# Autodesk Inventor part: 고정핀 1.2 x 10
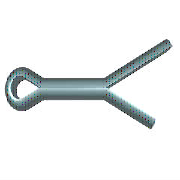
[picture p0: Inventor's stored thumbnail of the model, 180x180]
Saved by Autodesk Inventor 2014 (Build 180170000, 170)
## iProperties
IsCustomPart: 1
Created: 2012-02
Part Number: 고정핀 1.2 x 10
Material: 강철
Description: 분할 핀
Document SubType Name: Modeling
Standard: ISO 1234
Designer: test
Standard Revision: Second edition 1997-11-01
Standards Organization: ISO
Language: ko-KR
Size Designation: 1.2 x 10
Categories: <MemberInstance><Categories><Category DisplayName="조임쇠" InternalName="e4da775c-781d-43d5-af7c-5136215cf5a6" Mnemonic="FSTN"><Category DisplayName="핀" InternalNa
Density: 7.85 g/cm^3
Appearance: 강철
Author: test
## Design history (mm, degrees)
sketch "스케치1"
  geometry: L1 (0, 0.5)-(5, 0.5); L2 (0, -0.5)-(5, -0.5); L3 (5, 0.5)-(10, 2.416); L4 (10, 2.416)-(10.167, 1.98); L5 (10.167, 1.98)-(5, 0); L6 (5, 0)-(12.667, -2.937); L7 (12.667, -2.937)-(12.5, -3.373); L8 (12.5, -3.373)-(5, -0.5); L9 (0, 0)-(-1.875, -0.484); L10 (0, 0)-(-1.875, 0.484); L11 (0, 0.5)-(0, -0.5); L12 (0, 0.5)-(-1.742, 0.966); L13 (0, -0.5)-(-1.742, -0.966); L14 (-3, 0)-(5, 0); L15 (5, 0.5)-(5, -0.5); A1 r 1 centre (-2, 0) between (-1.742, 0.966) and (-1.742, -0.966); A2 r 0.5 centre (-2, 0) between (-1.875, 0.484) and (-1.875, -0.484); 1 further point
  constraints: 30 end point, 5 point on circle, 4 parallel, 4 perpendicular, 4 point on line, 4 tangent, 2 centre point, 2 midpoint, 1 coincident, 1 horizontal
  dimensions: "d0" = 5 distance of L1.start L1.end (= MSIAB); "d1" = 10 horizontal distance of L1.start L3.end (= SNLG); "d2" = 159.037 deg angle of L1 L3; "d3" = 159.037 deg angle of L2 L8; "d4" = 2.5 horizontal distance of L3.end L7.end (= LGDIF); "d5" = 0.5 radius of A2 (= -0.5 x SNND1 + 0.5 x KBR); "d6" = 1 radius of A1 (= 0.5 x KBR); "d7" = 0.5 distance from line of L1 L9.start (= 0.5 x SNND1); "d8" = 0.5 distance between parallel lines of L2 L14 (= 0.5 x SNND1); "d9" = 2 distance from line of L11 A1.centre (= KOL - 0.5 x KBR)
extrude "본체" new body sketch "스케치1" stored distance "d10" = 1 (= SNND1); taper "d11" = 0 deg
workaxis "Work Axis1"
workplane "Work Plane1"
workplane "Work Plane3"
sketch "스케치5"
  geometry: L1 (-12.625, 3.047)-(-5.065, 0.15) reference; L2 (-12.667, 2.937)-(-12.625, 3.047) reference; L3 (-5, 0)-(-12.667, 2.937) reference; L4 (-10.167, -1.98)-(-5, 0) reference; L5 (-10.125, -2.089)-(-10.167, -1.98) reference; L6 (-5.065, -0.15)-(-10.125, -2.089) reference; L7 (0.046, -0.15)-(-5.065, -0.15) reference; L8 (1.832, -0.628)-(0.046, -0.15) reference; L9 (0.046, 0.15)-(1.832, 0.628) reference; L10 (-5.065, 0.15)-(0.046, 0.15) reference; L11 (1.875, -0.484)-(0, 0) reference; L12 (0, 0)-(1.875, 0.484) reference; L13 (0, 0)-(-1.725, 0); A1 r 0.65 centre (2, 0) between (1.832, -0.628) and (1.832, 0.628) reference; A2 r 0.5 centre (2, 0) between (1.875, -0.484) and (1.875, 0.484) reference
  constraints: 2 end point, 1 parallel
body "Solid1"
fillet "모깎기" dims "d12" = 0.35 (= 0.35 x SNND1)
other parameters: "SNND" = 1.2 [user parameter], "SNLG" = 10 [user parameter; used in 1 equation term], "SNND1" = 1 [user parameter; used in 5 equation terms], "KBR" = 2 [user parameter; used in 3 equation terms], "KOL" = 3 [user parameter; used in 1 equation term], "LGDIF" = 2.5 [user parameter; used in 1 equation term], "MSIAB" = 5 [user parameter; used in 1 equation term], "d15" = 0, "d16" = 0, "d17" = 0, "NNDMAX" = 5.5 [user parameter], "DSH" = 2.6 [user parameter], "NNDMIN" = 4.5 [user parameter]
